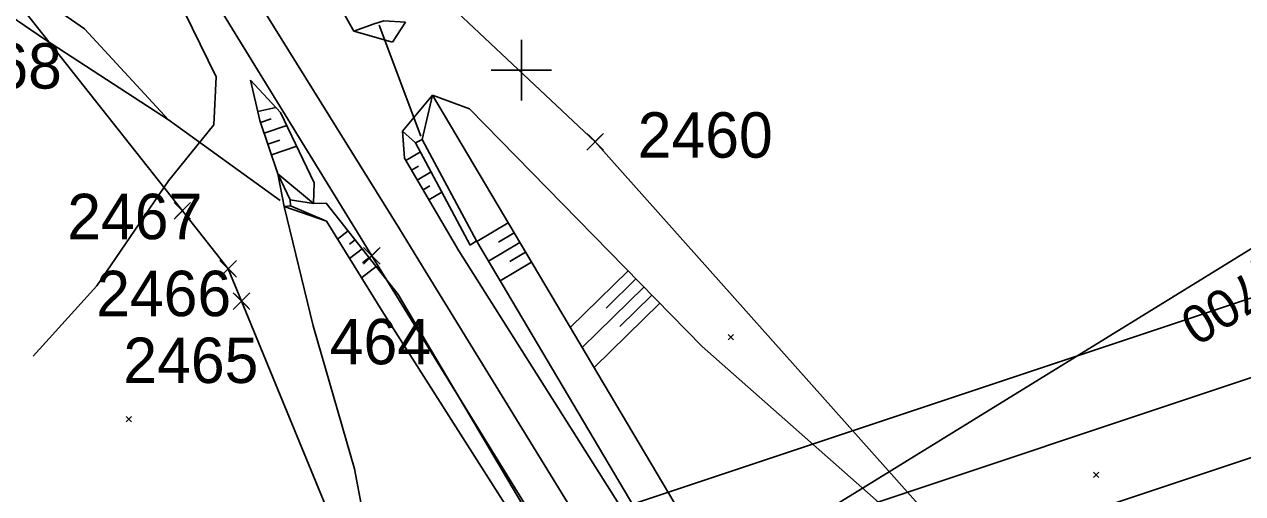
# Model space of a CAD drawing. Extents: x -866402 to -860377, y -1041908 to -1038598.
# Drawn here: x -864732.9 to -864652.3, y -1041328 to -1041297 of the extents above; entities that cross this region are included whole.
import ezdxf

# ---------------------------------------------------------------- set-up
doc = ezdxf.new("R2010")
doc.units = 0
for name, color, linetype in [('PS 02 trasa', 7, 'Continuous'), ('SZDC', 7, 'Continuous'), ('Vrstva 1', 7, 'Continuous'), ('Vrstva 19', 7, 'Continuous'), ('Vrstva 48', 7, 'Continuous'), ('Vrstva 49', 7, 'Continuous'), ('Vrstva 5', 7, 'Continuous'), ('Vrstva 60', 7, 'Continuous')]:
    doc.layers.add(name, color=color, linetype=linetype)

msp = doc.modelspace()

# ---------------------------------------------------------------- linework, layer by layer
at = {"layer": 'PS 02 trasa'}
msp.add_lwpolyline([(-864722.992, -1041290.927), (-864709.891, -1041312.256), (-864696.818, -1041333.455), (-864683.647, -1041354.845), (-864669.989, -1041375.841), (-864670.047, -1041375.753), (-864654.196, -1041396.064), (-864636.993, -1041413.96), (-864617.087, -1041430.25), (-864595.729, -1041443.847), (-864573.114, -1041455.135), (-864549.386, -1041463.847), (-864525.459, -1041469.721), (-864500.135, -1041472.829), (-864472.89, -1041473.438), (-864449.699, -1041470.862), (-864425.036, -1041465.796), (-864401.282, -1041457.793)], dxfattribs=at)
at = {"layer": 'SZDC'}
for points in [[(-864707.88, -1041292.731), (-864695.12, -1041304.731), (-864665.06, -1041338.43)], [(-864702.863, -1041353.237), (-864705.721, -1041346.294), (-864707.188, -1041342.73), (-864718.497, -1041315.253), (-864719.377, -1041313.116), (-864722.414, -1041309.283), (-864732.75, -1041296.241)]]:
    msp.add_lwpolyline(points, dxfattribs=at)
at = {"layer": 'Vrstva 1'}
for points in [[(-864678.843, -1041637.084), (-863881.875, -1041371.706), (-863975.703, -1041089.927), (-864772.671, -1041355.305)], [(-863888.199, -1041368.542), (-864675.679, -1041630.76), (-864766.347, -1041358.469), (-863978.867, -1041096.25)], [(-864672.518, -1041624.443), (-864089.016, -1041430.146), (-864176.529, -1041167.333), (-864760.03, -1041361.63)]]:
    msp.add_lwpolyline(points, close=True, dxfattribs=at)
msp.add_lwpolyline([(-864716.892, -1041296.273), (-864708.057, -1041310.483), (-864706.352, -1041313.25), (-864684.947, -1041348.104)], dxfattribs=at)
at = {"layer": 'Vrstva 19'}
for p, q in [((-864709.396, -1041297.019), (-864706.649, -1041304.368)), ((-864723.333, -1041303.276), (-864715.947, -1041308.604))]:
    msp.add_line(p, q, dxfattribs=at)
at = {"layer": 'Vrstva 48'}
for p, q in [((-864717.428, -1041302.734), (-864716.228, -1041302.46)), ((-864717.246, -1041303.461), (-864716.537, -1041303.22)), ((-864717.006, -1041304.171), (-864715.503, -1041303.662)), ((-864716.765, -1041304.882), (-864715.972, -1041304.613)), ((-864716.524, -1041305.592), (-864714.855, -1041305.026)), ((-864707.642, -1041305.969), (-864706.677, -1041305.401)), ((-864707.262, -1041306.616), (-864706.792, -1041306.339)), ((-864706.881, -1041307.262), (-864705.969, -1041306.725)), ((-864706.501, -1041307.908), (-864706.058, -1041307.648)), ((-864706.12, -1041308.555), (-864705.261, -1041308.049)), ((-864711.454, -1041310.616), (-864712.148, -1041311.16)), ((-864700.863, -1041310.096), (-864702.936, -1041311.326)), ((-864700.48, -1041310.741), (-864701.517, -1041311.356)), ((-864710.991, -1041311.206), (-864711.371, -1041311.504)), ((-864700.097, -1041311.386), (-864702.171, -1041312.617)), ((-864710.529, -1041311.796), (-864711.353, -1041312.443)), ((-864710.066, -1041312.386), (-864710.51, -1041312.735)), ((-864699.715, -1041312.031), (-864700.752, -1041312.646)), ((-864709.603, -1041312.977), (-864710.558, -1041313.726)), ((-864699.332, -1041312.676), (-864701.406, -1041313.907)), ((-864692.949, -1041313.256), (-864696.769, -1041316.992)), ((-864692.425, -1041313.792), (-864694.4, -1041315.724)), ((-864691.9, -1041314.328), (-864695.981, -1041318.32)), ((-864690.851, -1041315.4), (-864695.193, -1041319.647)), ((-864691.376, -1041314.864), (-864693.482, -1041316.924))]:
    msp.add_line(p, q, dxfattribs=at)
at = {"layer": 'Vrstva 49'}
for p, q in [((-864707.656, -1041296.832), (-864708.529, -1041298.158)), ((-864708.529, -1041298.158), (-864711.086, -1041297.417)), ((-864705.87, -1041301.661), (-864707.864, -1041304.026)), ((-864706.567, -1041304.59), (-864705.87, -1041301.661)), ((-864707.864, -1041304.026), (-864707.736, -1041305.81)), ((-864706.994, -1041304.809), (-864707.864, -1041304.026)), ((-864706.567, -1041304.59), (-864706.994, -1041304.809)), ((-864706.994, -1041304.809), (-864703.382, -1041311.562)), ((-864715.284, -1041308.568), (-864716.097, -1041306.852)), ((-864715.672, -1041309.01), (-864716.097, -1041306.852)), ((-864715.672, -1041309.01), (-864715.252, -1041308.961)), ((-864715.672, -1041309.01), (-864712.88, -1041309.98)), ((-864713.739, -1041308.817), (-864715.284, -1041308.568)), ((-864715.284, -1041308.568), (-864715.252, -1041308.961)), ((-864712.88, -1041309.98), (-864715.252, -1041308.961)), ((-864713.739, -1041308.817), (-864712.896, -1041308.778)), ((-864703.382, -1041311.562), (-864702.962, -1041311.282)), ((-864686.331, -1041317.458), (-864685.977, -1041317.812)), ((-864686.331, -1041317.812), (-864685.977, -1041317.458)), ((-864726.123, -1041322.877), (-864725.769, -1041323.231)), ((-864726.123, -1041323.231), (-864725.769, -1041322.877)), ((-864662.164, -1041326.549), (-864661.81, -1041326.903)), ((-864662.164, -1041326.903), (-864661.81, -1041326.549))]:
    msp.add_line(p, q, dxfattribs=at)
for points in [[(-864711.086, -1041297.417), (-864720.35, -1041280.962), (-864722.547, -1041279.645), (-864734.116, -1041262.124), (-864742.021, -1041252.544), (-864752.884, -1041238.849), (-864764.182, -1041225.554), (-864775.955, -1041212.54), (-864790.19, -1041198.754), (-864793.228, -1041195.603)], [(-864793.437, -1041207.363), (-864783.388, -1041220.434), (-864772.12, -1041233.856), (-864763.356, -1041244.409), (-864749.059, -1041257.506), (-864742.052, -1041268.07), (-864722.796, -1041295.061), (-864720.178, -1041300.441), (-864720.323, -1041303.621)], [(-864723.333, -1041303.276), (-864728.888, -1041297.269), (-864740.766, -1041289.045), (-864751.777, -1041283.028), (-864760.066, -1041279.441), (-864774.63, -1041272.997), (-864782.99, -1041262.254), (-864802.684, -1041242.227)], [(-864723.333, -1041303.276), (-864731.52, -1041297.958), (-864741.851, -1041290.907), (-864753.09, -1041284.695), (-864761.148, -1041280.868), (-864774.981, -1041275.731)], [(-864711.086, -1041297.417), (-864709.735, -1041296.93), (-864709.1, -1041296.75), (-864707.656, -1041296.832)], [(-864713.739, -1041308.817), (-864713.706, -1041307.446), (-864715.915, -1041302.795), (-864717.899, -1041300.67)], [(-864717.899, -1041300.67), (-864717.293, -1041303.323), (-864716.097, -1041306.852), (-864713.739, -1041308.817)], [(-864642.097, -1041392.43), (-864648.644, -1041382.044), (-864652.237, -1041369.569), (-864658.908, -1041353.879), (-864666.425, -1041339.474), (-864675.789, -1041329.057), (-864688.052, -1041318.262), (-864703.419, -1041302.552), (-864705.87, -1041301.661)], [(-864705.87, -1041301.661), (-864677.362, -1041349.687), (-864668.597, -1041366.753), (-864657.663, -1041382.253), (-864652.622, -1041388.515), (-864648.777, -1041393.343)], [(-864720.323, -1041303.621), (-864723.319, -1041307.308), (-864728.06, -1041314.254), (-864732.284, -1041318.883)], [(-864648.777, -1041393.343), (-864653.196, -1041388.658), (-864658.037, -1041382.504), (-864669.504, -1041367.486), (-864679.41, -1041351.023), (-864702.962, -1041311.282), (-864706.567, -1041304.59)], [(-864707.736, -1041305.81), (-864704.126, -1041311.941), (-864679.41, -1041351.023)], [(-864715.672, -1041309.01), (-864713.763, -1041316.891), (-864711.039, -1041326.342), (-864708.492, -1041339.773), (-864702.915, -1041347.003), (-864696.162, -1041359.156), (-864686.82, -1041367.888), (-864664.971, -1041387.782), (-864661.042, -1041389.903)], [(-864712.896, -1041308.778), (-864708.149, -1041314.83), (-864684.836, -1041354.196)], [(-864684.836, -1041354.196), (-864709.228, -1041315.87), (-864712.88, -1041309.98)]]:
    msp.add_lwpolyline(points, dxfattribs=at)
at = {"layer": 'Vrstva 5'}
for p, q in [((-864700, -1041298), (-864700, -1041302)), ((-864702, -1041300), (-864698, -1041300)), ((-864689.167, -1041334.825), (-864645.189, -1041307.76))]:
    msp.add_line(p, q, dxfattribs=at)
at = {"layer": 'Vrstva 60'}
for p, q in [((-864694.67, -1041305.181), (-864695.67, -1041304.181)), ((-864694.67, -1041304.281), (-864695.67, -1041305.281)), ((-864695.57, -1041305.181), (-864694.57, -1041304.181)), ((-864695.57, -1041304.281), (-864694.57, -1041305.281)), ((-864695.12, -1041304.731), (-864695.12, -1041304.731)), ((-864721.964, -1041309.733), (-864722.964, -1041308.733)), ((-864721.964, -1041308.833), (-864722.964, -1041309.833)), ((-864722.864, -1041309.733), (-864721.864, -1041308.733)), ((-864722.864, -1041308.833), (-864721.864, -1041309.833)), ((-864722.414, -1041309.283), (-864722.414, -1041309.283)), ((-864709.441, -1041312.706), (-864710.441, -1041311.706)), ((-864709.441, -1041311.806), (-864710.441, -1041312.806)), ((-864710.341, -1041312.706), (-864709.341, -1041311.706)), ((-864710.341, -1041311.806), (-864709.341, -1041312.806)), ((-864709.891, -1041312.256), (-864709.891, -1041312.256)), ((-864718.927, -1041313.566), (-864719.927, -1041312.566)), ((-864718.927, -1041312.666), (-864719.927, -1041313.666)), ((-864719.827, -1041313.566), (-864718.827, -1041312.566)), ((-864719.827, -1041312.666), (-864718.827, -1041313.666)), ((-864719.377, -1041313.116), (-864719.377, -1041313.116)), ((-864718.047, -1041315.703), (-864719.047, -1041314.703)), ((-864718.047, -1041314.803), (-864719.047, -1041315.803)), ((-864718.947, -1041315.703), (-864717.947, -1041314.703)), ((-864718.947, -1041314.803), (-864717.947, -1041315.803)), ((-864718.497, -1041315.253), (-864718.497, -1041315.253))]:
    msp.add_line(p, q, dxfattribs=at)

# ---------------------------------------------------------------- texts
at = {"layer": 'Vrstva 5'}
msp.add_text('km 5,700', height=2.5, rotation=211.6093, dxfattribs=at).set_placement((-864644.942, -1041308.936))
at = {"layer": 'Vrstva 60'}
for s, p in [('2468', (-864739.305, -1041301.219)), ('2460', (-864692.305, -1041305.781)), ('2467', (-864730.022, -1041311.166)), ('2466', (-864728.109, -1041316.252)), ('464', (-864712.667, -1041319.432)), ('2465', (-864726.312, -1041320.667))]:
    msp.add_text(s, height=3, dxfattribs=at).set_placement(p)

doc.saveas('drawing.dxf')
